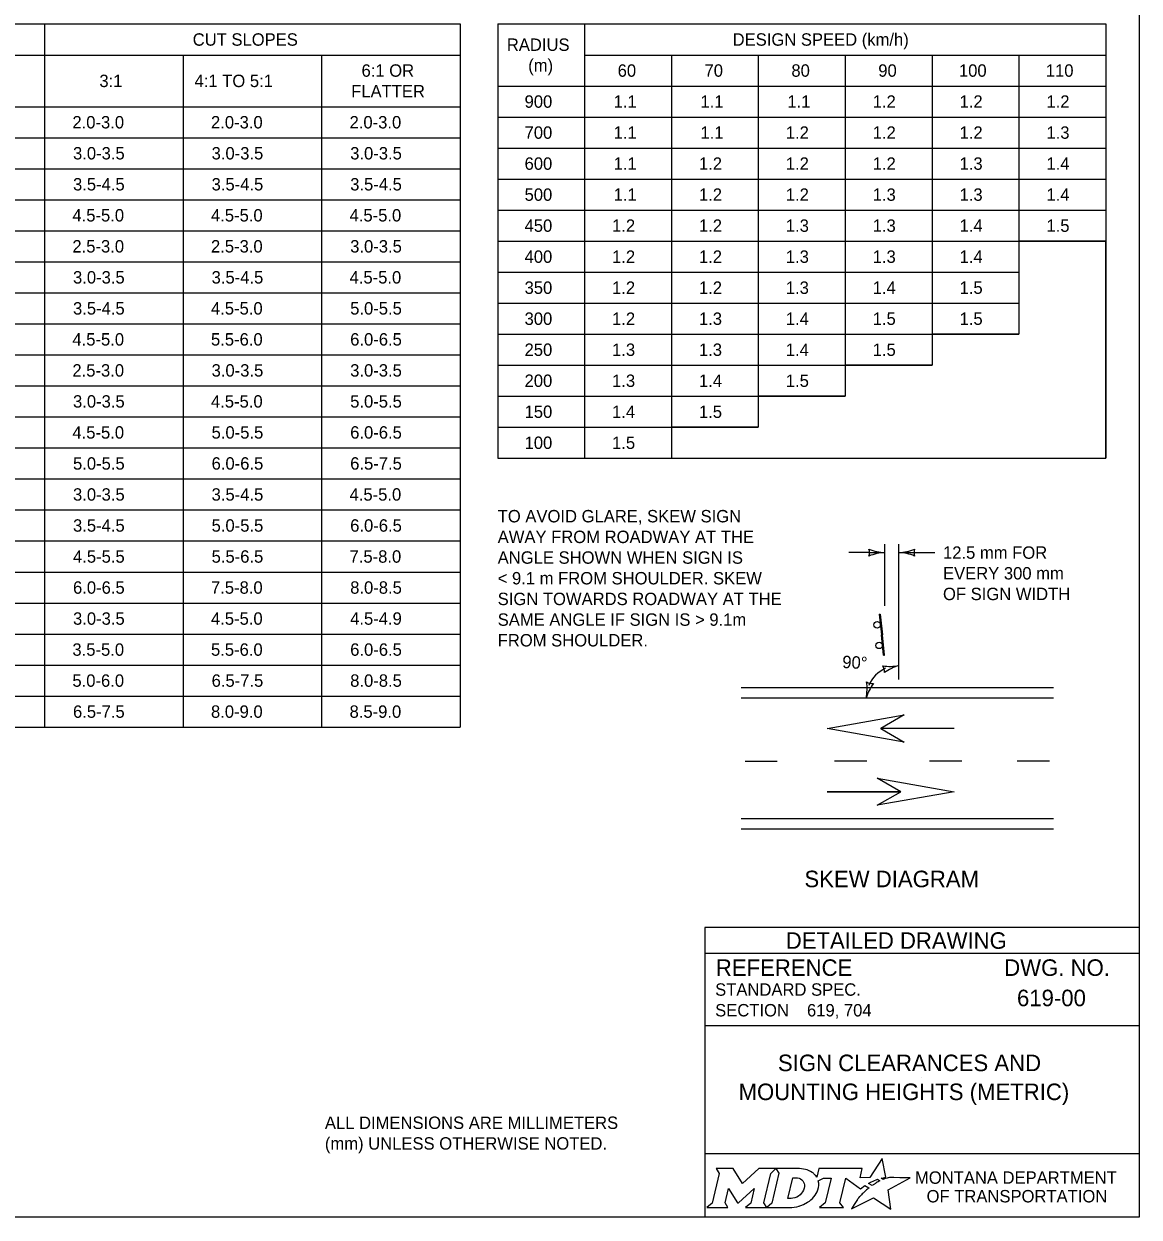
# Model space of a CAD drawing. Extents: x 49991.4 to 50021, y 49987.6 to 50011.4.
# Drawn here: x 50011.36 to 50016.75, y 49987.8 to 49993.57 of the extents above; entities that cross this region are included whole.
import ezdxf

# ---------------------------------------------------------------- set-up
doc = ezdxf.new("R2010")
doc.units = 0
for name, color, linetype in [('Default', 7, 'Continuous'), ('Level 1', 7, 'Continuous'), ('Level 2', 7, 'Continuous'), ('Level 3', 7, 'Continuous'), ('Level 5', 7, 'Continuous')]:
    doc.layers.add(name, color=color, linetype=linetype)

msp = doc.modelspace()

# ---------------------------------------------------------------- linework, layer by layer
at = {"layer": 'Default'}
for points in [[(50015.5126, 49987.9811), (50015.5023, 49987.9867), (50015.5139, 49987.9895), (50015.5255, 49987.9915), (50015.5081, 49988.0816), (50015.4486, 49987.9903), (50015.4013, 49987.9896), (50015.4116, 49988.0337), (50015.2024, 49988.0338), (50015.1923, 49987.9913), (50015.1865, 49987.9996)], [(50014.7056, 49988.0338), (50014.7197, 49988.0104), (50014.6862, 49987.8671), (50014.6605, 49987.8446), (50014.7621, 49987.8446), (50014.7486, 49987.8674), (50014.7648, 49987.9375), (50014.8085, 49987.8685), (50014.8138, 49987.8685), (50014.8889, 49987.938), (50014.8725, 49987.8669), (50014.8478, 49987.8449), (50014.9494, 49987.8449), (50014.9356, 49987.8682), (50014.9688, 49988.0106)], [(50014.9688, 49988.0106), (50014.9941, 49988.0338), (50014.9117, 49988.0338), (50014.8321, 49987.9608), (50014.7876, 49988.0335), (50014.7056, 49988.0338)], [(50015.1077, 49988.0338), (50014.9941, 49988.0338), (50015.0088, 49988.0109), (50014.9749, 49987.8671), (50014.9494, 49987.8449), (50015.06, 49987.8449)], [(50015.1317, 49987.9471), (50015.1305, 49987.939), (50015.1273, 49987.9297), (50015.1231, 49987.9215), (50015.1175, 49987.914), (50015.111, 49987.9071), (50015.1031, 49987.9008), (50015.0948, 49987.8961), (50015.0857, 49987.8922), (50015.0766, 49987.8899), (50015.0674, 49987.889), (50015.0515, 49987.889), (50015.0751, 49987.989), (50015.0911, 49987.989), (50015.0987, 49987.9884), (50015.1063, 49987.9865), (50015.1129, 49987.9835), (50015.119, 49987.9793), (50015.1238, 49987.9743), (50015.1275, 49987.9683), (50015.1302, 49987.9621), (50015.1318, 49987.9547), (50015.1318, 49987.9517), (50015.1317, 49987.9471)], [(50015.1991, 49987.9747), (50015.2237, 49987.9878), (50015.2606, 49987.9878), (50015.232, 49987.8673), (50015.2045, 49987.8446), (50015.3207, 49987.8446), (50015.3037, 49987.8675), (50015.3319, 49987.9877), (50015.4032, 49987.936), (50015.4243, 49987.9511), (50015.444, 49987.9402)], [(50015.3882, 49987.8843), (50015.3729, 49987.8599), (50015.3682, 49987.8524), (50015.3624, 49987.8438), (50015.3601, 49987.8395), (50015.4654, 49987.8926), (50015.5493, 49987.8375), (50015.5362, 49987.9302), (50015.6431, 49987.9886), (50015.5938, 49987.9894), (50015.5637, 49987.9898), (50015.5429, 49987.9901), (50015.5361, 49987.9886), (50015.5312, 49987.9874), (50015.5228, 49987.9851), (50015.5126, 49987.9811)], [(50015.4622, 49987.9535), (50015.4598, 49987.9518), (50015.4415, 49987.9614), (50015.4518, 49987.9671), (50015.4559, 49987.9693), (50015.4645, 49987.9733), (50015.4702, 49987.9759), (50015.4781, 49987.9789), (50015.4854, 49987.9816), (50015.4972, 49987.9742), (50015.4932, 49987.9721), (50015.4886, 49987.9696), (50015.4844, 49987.9674), (50015.4794, 49987.9645), (50015.4775, 49987.9634), (50015.4748, 49987.9618), (50015.4723, 49987.9604), (50015.47, 49987.9588), (50015.4674, 49987.957), (50015.4647, 49987.9552), (50015.4622, 49987.9535)], [(50015.1057, 49987.8522), (50015.1141, 49987.8548), (50015.1271, 49987.8602), (50015.1475, 49987.8712)], [(50015.4021, 49987.9004), (50015.4021, 49987.9004)]]:
    msp.add_lwpolyline(points, dxfattribs=at)
for centre, radius, start, end in [((50015.1308, 49987.9554), 0.0709, 339.53292, 15.85821), ((50015.0868, 49987.9727), 0.1183, 300.91025, 339.13831)]:
    msp.add_arc(centre, radius, start, end, dxfattribs=at)
for centre, major_axis, ratio, start_param, end_param in [((50015.1056, 49987.9864), (0.0834, -0.0037), 0.568097, 0.61298, 1.570796), ((50015.1612, 49987.9937), (0.0361, -0.0295), 0.469099, 1.225588, 1.570796), ((50015.4119, 49987.9106), (-0.0098, -0.0102), 0.016458, 3.141593, 6.279097), ((50015.4329, 49987.9305), (-0.0112, -0.0097), 0.021651, 3.157348, 6.283185), ((50015.0603, 49987.9932), (0, 0.1484), 0.987302, 3.139398, 3.456847), ((50015.3952, 49987.8923), (-0.00694, -0.00806), 0.008222, 0, 3.137361)]:
    msp.add_ellipse(centre, major_axis=major_axis, ratio=ratio, start_param=start_param, end_param=end_param, dxfattribs=at)
at = {"layer": 'Level 1'}
for p, q in [((50015.4937, 49990.7139), (50015.4987, 49990.7145)), ((50015.4937, 49990.7139), (50015.5041, 49990.6148)), ((50015.4943, 49990.714), (50015.5047, 49990.6148)), ((50015.4949, 49990.7141), (50015.5053, 49990.6149)), ((50015.4955, 49990.7141), (50015.5059, 49990.615)), ((50015.4962, 49990.7142), (50015.5066, 49990.615)), ((50015.4968, 49990.7143), (50015.5072, 49990.6151)), ((50015.4975, 49990.7143), (50015.5079, 49990.6152)), ((50015.4981, 49990.7144), (50015.5085, 49990.6152)), ((50015.4987, 49990.7145), (50015.5091, 49990.6153)), ((50015.5091, 49990.6153), (50015.5041, 49990.6148)), ((50015.5091, 49990.6153), (50015.5041, 49990.6148)), ((50015.5145, 49990.5155), (50015.5041, 49990.6148)), ((50015.5151, 49990.5156), (50015.5047, 49990.6148)), ((50015.5157, 49990.5157), (50015.5053, 49990.6149)), ((50015.5163, 49990.5157), (50015.5059, 49990.615)), ((50015.517, 49990.5158), (50015.5066, 49990.615)), ((50015.5176, 49990.5159), (50015.5072, 49990.6151)), ((50015.5183, 49990.5159), (50015.5079, 49990.6152)), ((50015.5189, 49990.516), (50015.5085, 49990.6152)), ((50015.5195, 49990.5161), (50015.5091, 49990.6153)), ((50015.5145, 49990.5155), (50015.5195, 49990.5161)), ((50016.3367, 49990.359), (50014.8268, 49990.359)), ((50015.5884, 49990.309), (50014.8268, 49990.309)), ((50016.3367, 49990.309), (50015.5884, 49990.309)), ((50015.8563, 49990.1623), (50015.5005, 49990.1623)), ((50014.845, 49990.0031), (50015.0006, 49990.0031)), ((50015.433, 49990.0031), (50015.2774, 49990.0031)), ((50015.893, 49990.0031), (50015.7374, 49990.0031)), ((50016.3168, 49990.0031), (50016.1612, 49990.0031)), ((50015.2417, 49989.8566), (50015.5975, 49989.8566)), ((50015.2417, 49989.8562), (50015.5975, 49989.8562)), ((50014.8268, 49989.7263), (50016.3367, 49989.7263)), ((50014.8268, 49989.6763), (50016.3367, 49989.6763))]:
    msp.add_line(p, q, dxfattribs=at)
for points in [[(49999.3835, 49998.9992), (50016.7501, 49998.9992), (50016.7501, 49987.7988), (49999.3835, 49987.7988)], [(50015.6143, 49990.0963), (50015.2419, 49990.1619), (50015.6143, 49990.2279), (50015.5007, 49990.1619)], [(50015.4839, 49989.9218), (50015.8563, 49989.8562), (50015.4839, 49989.7902), (50015.5975, 49989.8562)]]:
    msp.add_lwpolyline(points, close=True, dxfattribs=at)
for centre in [(50015.4831, 49990.6627), (50015.4935, 49990.5634)]:
    msp.add_circle(centre, 0.0156, dxfattribs=at)
at = {"layer": 'Level 2'}
for p, q in [((50008.2279, 49993.5684), (50013.4679, 49993.5684)), ((50011.4579, 49993.5684), (50011.4579, 49990.1684)), ((50013.4679, 49993.5684), (50013.4679, 49990.1684)), ((50013.649, 49993.5684), (50013.649, 49991.4684)), ((50013.649, 49993.5684), (50016.589, 49993.5684)), ((50014.069, 49993.5684), (50014.069, 49991.4684)), ((50016.589, 49993.5684), (50016.589, 49991.4684)), ((50009.4479, 49993.4184), (50013.4679, 49993.4184)), ((50012.1279, 49993.4184), (50012.1279, 49990.1684)), ((50012.7979, 49993.4184), (50012.7979, 49990.1684)), ((50014.069, 49993.4184), (50016.589, 49993.4184)), ((50014.489, 49993.4184), (50014.489, 49991.4684)), ((50014.909, 49993.4184), (50014.909, 49991.6184)), ((50015.329, 49993.4184), (50015.329, 49991.7684)), ((50015.749, 49993.4184), (50015.749, 49991.9184)), ((50016.169, 49993.4184), (50016.169, 49992.0684)), ((50013.649, 49993.2684), (50016.589, 49993.2684)), ((50008.2279, 49993.1684), (50013.4679, 49993.1684)), ((50013.649, 49993.1184), (50016.589, 49993.1184)), ((50008.8379, 49993.0184), (50013.4679, 49993.0184)), ((50013.649, 49992.9684), (50016.589, 49992.9684)), ((50008.8379, 49992.8684), (50013.4679, 49992.8684)), ((50013.649, 49992.8184), (50016.589, 49992.8184)), ((50008.8379, 49992.7184), (50013.4679, 49992.7184)), ((50013.649, 49992.6684), (50016.589, 49992.6684)), ((50008.2279, 49992.5684), (50013.4679, 49992.5684)), ((50013.649, 49992.5184), (50016.589, 49992.5184)), ((50016.589, 49992.5184), (50016.169, 49992.5184)), ((50016.169, 49992.5184), (50016.169, 49992.0684)), ((50016.589, 49991.4684), (50016.589, 49992.5184)), ((50008.8379, 49992.4184), (50013.4679, 49992.4184)), ((50013.649, 49992.3684), (50016.169, 49992.3684)), ((50008.8379, 49992.2684), (50013.4679, 49992.2684)), ((50013.649, 49992.2184), (50016.169, 49992.2184)), ((50008.8379, 49992.1184), (50013.4679, 49992.1184)), ((50013.649, 49992.0684), (50016.169, 49992.0684)), ((50016.169, 49992.0684), (50015.749, 49992.0684)), ((50015.749, 49992.0684), (50015.749, 49991.9184)), ((50008.2279, 49991.9684), (50013.4679, 49991.9684)), ((50013.649, 49991.9184), (50015.749, 49991.9184)), ((50015.749, 49991.9184), (50015.329, 49991.9184)), ((50015.329, 49991.9184), (50015.329, 49991.7684)), ((50008.8379, 49991.8184), (50013.4679, 49991.8184)), ((50013.649, 49991.7684), (50015.329, 49991.7684)), ((50015.329, 49991.7684), (50014.909, 49991.7684)), ((50014.909, 49991.7684), (50014.909, 49991.6184)), ((50008.8379, 49991.6684), (50013.4679, 49991.6684)), ((50013.649, 49991.6184), (50014.909, 49991.6184)), ((50014.909, 49991.6184), (50014.489, 49991.6184)), ((50014.489, 49991.6184), (50014.489, 49991.4684)), ((50008.8379, 49991.5184), (50013.4679, 49991.5184)), ((50013.649, 49991.4684), (50016.589, 49991.4684)), ((50014.489, 49991.4684), (50016.589, 49991.4684)), ((50008.2279, 49991.3684), (50013.4679, 49991.3684)), ((50008.8379, 49991.2184), (50013.4679, 49991.2184)), ((50008.8379, 49991.0684), (50013.4679, 49991.0684)), ((50008.8379, 49990.9184), (50013.4679, 49990.9184)), ((50008.2279, 49990.7684), (50013.4679, 49990.7684)), ((50008.8379, 49990.6184), (50013.4679, 49990.6184)), ((50008.8379, 49990.4684), (50013.4679, 49990.4684)), ((50008.8379, 49990.3184), (50013.4679, 49990.3184)), ((50008.2279, 49990.1684), (50013.4679, 49990.1684))]:
    msp.add_line(p, q, dxfattribs=at)
at = {"layer": 'Level 3'}
for p, q in [((50015.5201, 49990.7545), (50015.5201, 49991.0524)), ((50015.5885, 49990.399), (50015.5885, 49991.0524)), ((50015.4467, 49991.0124), (50015.3467, 49991.0124)), ((50015.4467, 49991.0124), (50015.5201, 49991.0124)), ((50015.5885, 49991.0124), (50015.6619, 49991.0124)), ((50015.6619, 49991.0124), (50015.7619, 49991.0124))]:
    msp.add_line(p, q, dxfattribs=at)
for centre, radius, start, end in [((50015.5293, 49991.2345), 0.2223, 247.45601, 267.63952), ((50015.3919, 49991.0124), 0.0548, 342.13882, 17.86118), ((50015.577, 49991.2451), 0.233, 272.82731, 292.07716), ((50015.7167, 49991.0124), 0.0548, 162.13882, 197.86118), ((50015.5316, 49990.7797), 0.233, 92.82731, 112.07716), ((50015.5793, 49990.7903), 0.2223, 67.45601, 87.63952), ((50015.5885, 49990.309), 0.1574, 114.12299, 157.0534), ((50015.5445, 49990.6843), 0.2223, 261.22568, 281.40919), ((50015.464, 49990.4359), 0.0548, 355.90849, 31.63085), ((50015.6551, 49990.2431), 0.233, 106.59698, 125.84683), ((50015.202, 49990.354), 0.233, 348.87544, 8.12529), ((50015.644, 49990.2466), 0.2223, 143.50414, 163.68765), ((50015.4616, 49990.4334), 0.0548, 238.18695, 273.90931)]:
    msp.add_arc(centre, radius, start, end, dxfattribs=at)
at = {"layer": 'Level 5'}
for p, q in [((50016.7501, 49989.1988), (50014.6501, 49989.1988)), ((50014.6501, 49989.1988), (50014.6501, 49987.7988)), ((50016.7501, 49989.0738), (50014.6501, 49989.0738)), ((50016.3862, 49988.8587), (50016.3862, 49988.8587)), ((50015.1444, 49988.7993), (50015.1444, 49988.7993)), ((50016.7501, 49988.7238), (50014.6501, 49988.7238)), ((50015.7001, 49988.4747), (50015.7001, 49988.4747)), ((50016.7501, 49988.1057), (50014.6501, 49988.1057))]:
    msp.add_line(p, q, dxfattribs=at)

# ---------------------------------------------------------------- texts
at = {"layer": 'Default'}
for s, p in [('MONTANA DEPARTMENT', (50015.6663, 49987.96)), ('OF TRANSPORTATION', (50015.7225, 49987.87))]:
    msp.add_text(s, height=0.06, dxfattribs=at).set_placement(p)
at = {"layer": 'Level 2'}
for s, height, p in [('CUT SLOPES', 0.06, (50012.1745, 49993.4634)), ('DESIGN SPEED (km/h)', 0.06, (50014.7849, 49993.4634)), ('RADIUS', 0.06, (50013.6932, 49993.4384)), ('(m)', 0.06, (50013.7966, 49993.3384)), ('6:1 OR', 0.06, (50012.9908, 49993.3134)), ('60', 0.06, (50014.229, 49993.3134)), ('70', 0.06, (50014.649, 49993.3134)), ('80', 0.06, (50015.069, 49993.3134)), ('90', 0.06, (50015.489, 49993.3134)), ('100', 0.06, (50015.879, 49993.3134)), ('110', 0.06, (50016.299, 49993.3134)), ('3:1', 0.06, (50011.7233, 49993.2634)), ('4:1 TO 5:1', 0.06, (50012.1833, 49993.2634)), ('FLATTER', 0.06, (50012.9407, 49993.2134)), ('900', 0.06, (50013.779, 49993.1634)), ('1.1', 0.06, (50014.2094, 49993.1634)), ('1.1', 0.06, (50014.6294, 49993.1634)), ('1.1', 0.06, (50015.0494, 49993.1634)), ('1.2', 0.06, (50015.462, 49993.1634)), ('1.2', 0.06, (50015.882, 49993.1634)), ('1.2', 0.06, (50016.302, 49993.1634)), ('2.0-3.0', 0.06, (50011.5929, 49993.0634)), ('2.0-3.0', 0.06, (50012.2629, 49993.0634)), ('2.0-3.0', 0.06, (50012.9329, 49993.0634)), ('700', 0.06, (50013.779, 49993.0134)), ('1.1', 0.06, (50014.2094, 49993.0134)), ('1.1', 0.06, (50014.6294, 49993.0134)), ('1.2', 0.06, (50015.042, 49993.0134)), ('1.2', 0.06, (50015.462, 49993.0134)), ('1.2', 0.06, (50015.882, 49993.0134)), ('1.3', 0.06, (50016.302, 49993.0134)), ('3.0-3.5', 0.06, (50011.5959, 49992.9134)), ('3.0-3.5', 0.06, (50012.2659, 49992.9134)), ('3.0-3.5', 0.06, (50012.9359, 49992.9134)), ('600', 0.06, (50013.779, 49992.8634)), ('1.1', 0.06, (50014.2094, 49992.8634)), ('1.2', 0.06, (50014.622, 49992.8634)), ('1.2', 0.06, (50015.042, 49992.8634)), ('1.2', 0.06, (50015.462, 49992.8634)), ('1.3', 0.06, (50015.882, 49992.8634)), ('1.4', 0.06, (50016.302, 49992.8634)), ('3.5-4.5', 0.06, (50011.5959, 49992.7634)), ('3.5-4.5', 0.06, (50012.2659, 49992.7634)), ('3.5-4.5', 0.06, (50012.9359, 49992.7634)), ('500', 0.06, (50013.779, 49992.7134)), ('1.1', 0.06, (50014.2094, 49992.7134)), ('1.2', 0.06, (50014.622, 49992.7134)), ('1.2', 0.06, (50015.042, 49992.7134)), ('1.3', 0.06, (50015.462, 49992.7134)), ('1.3', 0.06, (50015.882, 49992.7134)), ('1.4', 0.06, (50016.302, 49992.7134)), ('4.5-5.0', 0.06, (50011.5929, 49992.6134)), ('4.5-5.0', 0.06, (50012.2629, 49992.6134)), ('4.5-5.0', 0.06, (50012.9329, 49992.6134)), ('450', 0.06, (50013.779, 49992.5634)), ('1.2', 0.06, (50014.202, 49992.5634)), ('1.2', 0.06, (50014.622, 49992.5634)), ('1.3', 0.06, (50015.042, 49992.5634)), ('1.3', 0.06, (50015.462, 49992.5634)), ('1.4', 0.06, (50015.882, 49992.5634)), ('1.5', 0.06, (50016.302, 49992.5634)), ('2.5-3.0', 0.06, (50011.5929, 49992.4634)), ('2.5-3.0', 0.06, (50012.2629, 49992.4634)), ('3.0-3.5', 0.06, (50012.9359, 49992.4634)), ('400', 0.06, (50013.779, 49992.4134)), ('1.2', 0.06, (50014.202, 49992.4134)), ('1.2', 0.06, (50014.622, 49992.4134)), ('1.3', 0.06, (50015.042, 49992.4134)), ('1.3', 0.06, (50015.462, 49992.4134)), ('1.4', 0.06, (50015.882, 49992.4134)), ('3.0-3.5', 0.06, (50011.5959, 49992.3134)), ('3.5-4.5', 0.06, (50012.2659, 49992.3134)), ('4.5-5.0', 0.06, (50012.9329, 49992.3134)), ('350', 0.06, (50013.779, 49992.2634)), ('1.2', 0.06, (50014.202, 49992.2634)), ('1.2', 0.06, (50014.622, 49992.2634)), ('1.3', 0.06, (50015.042, 49992.2634)), ('1.4', 0.06, (50015.462, 49992.2634)), ('1.5', 0.06, (50015.882, 49992.2634)), ('3.5-4.5', 0.06, (50011.5959, 49992.1634)), ('4.5-5.0', 0.06, (50012.2629, 49992.1634)), ('5.0-5.5', 0.06, (50012.9359, 49992.1634)), ('300', 0.06, (50013.779, 49992.1134)), ('1.2', 0.06, (50014.202, 49992.1134)), ('1.3', 0.06, (50014.622, 49992.1134)), ('1.4', 0.06, (50015.042, 49992.1134)), ('1.5', 0.06, (50015.462, 49992.1134)), ('1.5', 0.06, (50015.882, 49992.1134)), ('4.5-5.0', 0.06, (50011.5929, 49992.0134)), ('5.5-6.0', 0.06, (50012.2629, 49992.0134)), ('6.0-6.5', 0.06, (50012.9359, 49992.0134)), ('250', 0.06, (50013.779, 49991.9634)), ('1.3', 0.06, (50014.202, 49991.9634)), ('1.3', 0.06, (50014.622, 49991.9634)), ('1.4', 0.06, (50015.042, 49991.9634)), ('1.5', 0.06, (50015.462, 49991.9634)), ('2.5-3.0', 0.06, (50011.5929, 49991.8634)), ('3.0-3.5', 0.06, (50012.2659, 49991.8634)), ('3.0-3.5', 0.06, (50012.9359, 49991.8634)), ('200', 0.06, (50013.779, 49991.8134)), ('1.3', 0.06, (50014.202, 49991.8134)), ('1.4', 0.06, (50014.622, 49991.8134)), ('1.5', 0.06, (50015.042, 49991.8134)), ('3.0-3.5', 0.06, (50011.5959, 49991.7134)), ('4.5-5.0', 0.06, (50012.2629, 49991.7134)), ('5.0-5.5', 0.06, (50012.9359, 49991.7134)), ('150', 0.06, (50013.779, 49991.6634)), ('1.4', 0.06, (50014.202, 49991.6634)), ('1.5', 0.06, (50014.622, 49991.6634)), ('4.5-5.0', 0.06, (50011.5929, 49991.5634)), ('5.0-5.5', 0.06, (50012.2659, 49991.5634)), ('6.0-6.5', 0.06, (50012.9359, 49991.5634)), ('100', 0.06, (50013.779, 49991.5134)), ('1.5', 0.06, (50014.202, 49991.5134)), ('5.0-5.5', 0.06, (50011.5959, 49991.4134)), ('6.0-6.5', 0.06, (50012.2659, 49991.4134)), ('6.5-7.5', 0.06, (50012.9359, 49991.4134)), ('3.0-3.5', 0.06, (50011.5959, 49991.2634)), ('3.5-4.5', 0.06, (50012.2659, 49991.2634)), ('4.5-5.0', 0.06, (50012.9329, 49991.2634)), ('TO AVOID GLARE, SKEW SIGN', 0.06, (50013.649, 49991.1584)), ('3.5-4.5', 0.06, (50011.5959, 49991.1134)), ('5.0-5.5', 0.06, (50012.2659, 49991.1134)), ('6.0-6.5', 0.06, (50012.9359, 49991.1134)), ('AWAY FROM ROADWAY AT THE', 0.06, (50013.649, 49991.0584)), ('4.5-5.5', 0.06, (50011.5959, 49990.9634)), ('5.5-6.5', 0.06, (50012.2659, 49990.9634)), ('7.5-8.0', 0.06, (50012.9329, 49990.9634)), ('12.5 mm FOR ', 0.06, (50015.8019, 49990.9824)), ('ANGLE SHOWN WHEN SIGN IS', 0.06, (50013.649, 49990.9584)), ('< 9.1 m FROM SHOULDER. SKEW', 0.06, (50013.649, 49990.8584)), ('EVERY 300 mm ', 0.06, (50015.8019, 49990.8824)), ('6.0-6.5', 0.06, (50011.5959, 49990.8134)), ('7.5-8.0', 0.06, (50012.2629, 49990.8134)), ('8.0-8.5', 0.06, (50012.9359, 49990.8134)), ('SIGN TOWARDS ROADWAY AT THE', 0.06, (50013.649, 49990.7584)), ('OF SIGN WIDTH', 0.06, (50015.8019, 49990.7824)), ('3.0-3.5', 0.06, (50011.5959, 49990.6634)), ('4.5-5.0', 0.06, (50012.2629, 49990.6634)), ('4.5-4.9', 0.06, (50012.9357, 49990.6634)), ('SAME ANGLE IF SIGN IS > 9.1m', 0.06, (50013.649, 49990.6584)), ('FROM SHOULDER.', 0.06, (50013.649, 49990.5584)), ('3.5-5.0', 0.06, (50011.5929, 49990.5134)), ('5.5-6.0', 0.06, (50012.2629, 49990.5134)), ('6.0-6.5', 0.06, (50012.9359, 49990.5134)), ('5.0-6.0', 0.06, (50011.5929, 49990.3634)), ('6.5-7.5', 0.06, (50012.2659, 49990.3634)), ('8.0-8.5', 0.06, (50012.9359, 49990.3634)), ('6.5-7.5', 0.06, (50011.5959, 49990.2134)), ('8.0-9.0', 0.06, (50012.2629, 49990.2134)), ('8.5-9.0', 0.06, (50012.9329, 49990.2134)), ('SKEW DIAGRAM', 0.08, (50015.132, 49989.3941)), ('619-00', 0.08, (50016.1596, 49988.8187)), ('619, 704', 0.06, (50015.1444, 49988.7693)), ('SIGN CLEARANCES AND', 0.08, (50015.0039, 49988.5047)), ('MOUNTING HEIGHTS (METRIC)', 0.08, (50014.8136, 49988.3647)), ('ALL DIMENSIONS ARE MILLIMETERS', 0.06, (50012.8136, 49988.2252)), ('(mm) UNLESS OTHERWISE NOTED.', 0.06, (50012.8136, 49988.1252))]:
    msp.add_text(s, height=height, dxfattribs=at).set_placement(p)
msp.add_text('90°', height=0.06, rotation=357, dxfattribs=at).set_placement((50015.3137, 49990.4545))
at = {"layer": 'Level 5'}
for s, height, p in [('DETAILED DRAWING', 0.0799, (50015.0418, 49989.0963)), ('REFERENCE', 0.08, (50014.7037, 49988.9654)), ('DWG. NO.', 0.08, (50016.0979, 49988.9654)), ('STANDARD SPEC.', 0.06, (50014.7004, 49988.8694)), ('SECTION', 0.06, (50014.7004, 49988.7694))]:
    msp.add_text(s, height=height, dxfattribs=at).set_placement(p)

doc.saveas('drawing.dxf')
